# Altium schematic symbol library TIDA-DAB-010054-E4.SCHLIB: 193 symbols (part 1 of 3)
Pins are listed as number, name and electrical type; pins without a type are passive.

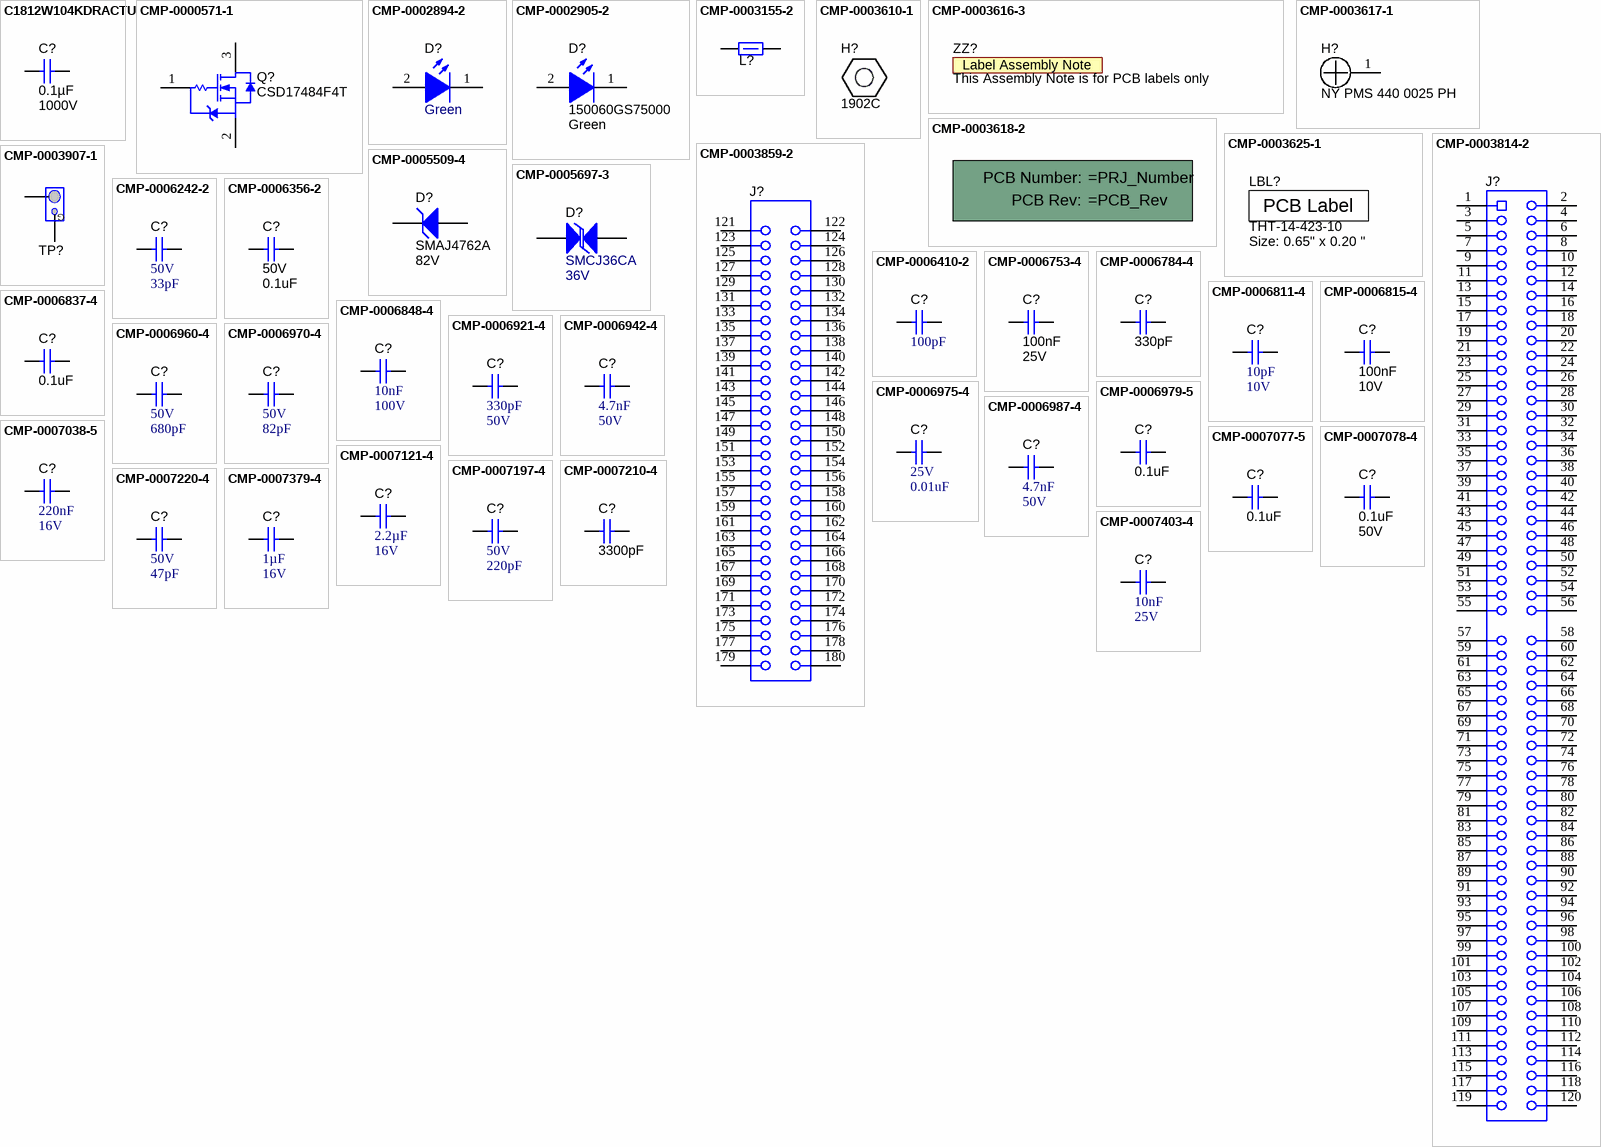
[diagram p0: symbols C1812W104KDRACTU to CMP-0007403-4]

## C1812W104KDRACTU
designator C?, comment ValueDisplayed: 0.1µF  Value2: 1000V  (hidden comment: 1812Y1K00104KXT)
CAP, CERM, 0.1 µF, 1000 V,+/- 10%, X7R, 1812; Manufacturer: Knowles Syfer; Polarized: N; CompType: Capacitor; Value: 0.1uF; U/M: EA; Cap_F: 0.0000001; Tolerance_%: 10; VDC_V: 1000; TaMin_C: -55; TaMax_C: 125; Cap_Case: 1812; SizeArea_mm2: 14.4; SizeAreaWB_mm2: 23.1; SizeX_mm: 4.5; SizeY_mm: 3.2; SizeZ_mm: 2.54; AEC Category: Q200; Green_Lifecycle: Active; Green_REACh: Passed
signal-integrity model Cap
simulation model Cap
footprint 1812_254
pins: 1, 2

## CMP-0000571-1
designator Q?, comment CSD17484F4T
MOSFET, N-CH, 30 V, 3 A, YJJ0003A (PICOSTAR-3); Alternate Manufacturer: None; Manufacturer: Texas Instruments; SizeZ_mm: 0.22; ChType: N; Value2: 0.92 nC; Value1: 0.12; VdsMax_V: 30V; SizeX_mm: 1; SizeY_mm: 0.6; Vgs_V: 12V; Value: 30V; Rdson45_ohm: 0.128; AEC Category: Q101; IdsMax_A: 3A; SizeAreaWB_mm2: 3.2; U/M: EA; QgTyp_nC: 0.92
footprint YJJ0003A (SMD, 3-Leads, Body 1x0.6mm)
pins: 1 G, 2 S, 3 D
1 alternate drawing of the same symbol

## CMP-0002894-2
designator D?, comment value Green  (hidden comment: 150060VS75000)
LED, Green, SMD; Manufacturer: Wurth Elektronik; Manufacturer: Wurth Electronics; Type: AlInGaP; Value2: 2V; Io_A: 20mA; Value1: W
footprint WL-SMCW_GREEN (WURTH)
pins: 1 K, 2 A

## CMP-0002905-2
designator D?, comment 150060GS75000  value Green
LED, Green, SMD; Manufacturer: Wurth Elektronik; Manufacturer: Wurth Electronics; Value1: W; Type: InGaN; Value2: 3.2V; Io_A: 20mA; Angle: 140; Tjmax_C: 85°C
footprint WL-SMCW_GREEN (WURTH)
pins: 1 K, 2 A

## CMP-0003155-2
designator L?, comment 74279228260  (value not drawn)
Ferrite Bead, 26 ohm @ 100 MHz, 6.5 A, 0603; Manufacturer: Wurth Elektronik; Ztyp@1GHz_Ohm: 35.506; ZTyp@100MHz_Ohm: 26; SizeAreaWB_mm2: 4.68; DCR_ohm: 5m; Value1: 0.005 ohm; Value: 26 ohm; Imax_A: 6.5A; SizeZ_mm: 1; SizeX_mm: 1.6; SizeY_mm: 0.8; SizeArea_mm2: 1.28
footprint 0603 (0603 from SM-752 data)
footprint 0603_HV (Ernesto recommended land pattern.  26 mil between pads.)
footprint 0603L (0603 from SM-752 data)
footprint 0603S
footprint 0603M (0603 from SM-752 data)
pins: 1, 2

## CMP-0003610-1
designator H?, comment 1902C
Standoff, Hex, 0.5"L #4-40 Nylon; Manufacturer: Keystone; Manufacturer: Keystone Electronics; CompType: Hardware
footprint Keystone_1902C (Hex Standoff, 4-40 threaded, nylon)

## CMP-0003616-3
designator ZZ?, comment This Assembly Note is for PCB labels only  (no BOM)
Key: AssemblyNoteLabel
footprint AssemblyNoteLabel (Assembly Note for PCB Labels)

## CMP-0003617-1
designator H?, comment NY PMS 440 0025 PH
Machine Screw, Round, #4-40 x 1/4, Nylon, Philips panhead; Manufacturer: B&F Fastener Supply; Manufacturer: B&F Fastener; CompType: Hardware
footprint NY PMS 440 0025 PH (4-40 nylon screw and mounting hole)
footprint NY PMS 440 0025 PH_3Donly (4-40 nylon screw)
pins: 1

## CMP-0003618-2
designator !PCB?, comment Printed Circuit Board  (value not drawn)  (mechanical)
Manufacturer: Any; CompType: PCB
1 alternate drawing of the same symbol

## CMP-0003625-1
designator LBL?, comment THT-14-423-10  Note: Size: 0.65" x 0.20 "
Thermal Transfer Printable Labels, 0.650" W x 0.200" H - 10,000 per roll; Manufacturer: Brady; CompType: Label
footprint Label_650x200 (Thermal Transfer Label)

## CMP-0003814-2
designator J?, comment HSEC8-160-01-L-DV-A-BL  (value not drawn)
C2000 controlCARD-120HSEC connector, SMT; Manufacturer: Samtec; Note: The pin numbering does not match Samtec datasheet
footprint controlCARD-120HSEC (Pads are not numbered according to Samtec datasheet.)
pins: 1, 2, 3, 4, 5, 6, 7, 8, 9, 10, 11, 12, 13, 14, 15, 16, 17, 18, 19, 20, 21, 22, 23, 24, 25, 26, 27, 28, 29, 30, 31, 32, 33, 34, 35, 36, 37, 38, 39, 40, 41, 42, 43, 44, 45, 46, 47, 48, 49, 50, 51, 52, 53, 54, 55, 56, 57, 58, 59, 60, 61, 62, 63, 64, 65, 66, 67, 68, 69, 70, 71, 72, 73, 74, 75, 76, 77, 78, 79, 80, 81, 82, 83, 84, 85, 86, 87, 88, 89, 90, 91, 92, 93, 94, 95, 96, 97, 98, 99, 100, 101, 102, 103, 104, 105, 106, 107, 108, 109, 110, 111, 112, 113, 114, 115, 116, 117, 118, 119, 120

## CMP-0003859-2
designator J?, comment HSEC8-130-01-L-DV-A  (value not drawn)
C2000 controlCARD-180HSEC (60-pin addon) connector, SMT; Manufacturer: Samtec; Note: The pin numbering does not match Samtec datasheet
footprint controlCARD-180HSEC-60pinAddon (Pads are not numbered according to datasheet.)
pins: 121, 122, 123, 124, 125, 126, 127, 128, 129, 130, 131, 132, 133, 134, 135, 136, 137, 138, 139, 140, 141, 142, 143, 144, 145, 146, 147, 148, 149, 150, 151, 152, 153, 154, 155, 156, 157, 158, 159, 160, 161, 162, 163, 164, 165, 166, 167, 168, 169, 170, 171, 172, 173, 174, 175, 176, 177, 178, 179, 180

## CMP-0003907-1
designator TP?, comment GNDP  (value not drawn)  (no BOM)
PIGTAIL; Manufacturer: Texas Instruments; Key: TESTPOINT_PIGTAIL; CompType: Test Point
footprint TESTPOINT_PIGTAIL (Pigtail)
pins: 1, 2

## CMP-0005509-4
designator D?, comment SMAJ4762A  value 82V
Diode, Zener, 82 V, 1 W, SMA; Manufacturer: Micro Commercial Components; Manufacturer: MCC; SizeAreaWB_mm2: 37.3428; SizeZ_mm: 2.87; SizeY_mm: 2.92; SizeArea_mm2: 16.3228; AEC Category: Q101; RJA_CperW: 100; SizeX_mm: 5.59; Power_W: 1W
footprint SMA (Molded Diode, 2-Leads, Body 4.3x2.6mm, IPC Medium Density, based on OnSemi component dimensions and land pattern)
pins: 1 K, 2 A

## CMP-0005697-3
designator D?, comment SMCJ36CA  value 36V
Diode, TVS, Bi, 36 V, 58.1 Vc, SMC; Manufacturer: Littelfuse; Ppk: 1.5kW; Vbr_Min: 40V; SizeX_mm: 8.13; SizeZ_mm: 2.6; SizeAreaWB_mm2: 83.2686; RJA_CperW: 75; AEC Category: Q101; Vbr_Max: 44.2V; SizeArea_mm2: 50.5686; Ipp: 25.9A; Vc: 58.1V; AEC Qualified: N; Value1: 1500W; SizeY_mm: 6.22
footprint SMC_Bi (SMC, no polarity mark)
pins: 1, 2

## CMP-0006242-2
designator C?, comment VDC_V: 50V  ValueDisplayed: 33pF  (hidden comment: C0402C330J5GAC)
CAP, CERM, 33 pF, 50 V, +/- 5%, C0G/NP0, 0402; Manufacturer: Kemet; TaMin_C: -55°C; Polarized: N; SizeAreaWB_mm2: 3; Value1: Unknown; U/M: EA; Value: 33pF; TaMax_C: 125°C; SizeZ_mm: 0.6; SizeX_mm: 1; SizeY_mm: 0.5; Cap_Case: 0402; CompType: Capacitor; AEC Category: Q200
footprint 0402 (0402 from SM-752 data)
footprint 0402S (Based on C0402S footprint from PADS legacy)
footprint 0402L (0402 from SM-752 data)
footprint 0402M (0402 from SM-752 data)
pins: 1, 2

## CMP-0006356-2
designator C?, comment VDC_V: 50V  ValueDisplayed: 0.1uF  (hidden comment: GCM155R71H104KE02D)
CAP, CERM, 0.1 uF, 50 V, +/- 10%, X7R, AEC-Q200 Grade 1, 0402; Manufacturer: MuRata; TaMin_C: -55°C; Polarized: N; SizeAreaWB_mm2: 3; Value1: Unknown; U/M: EA; Value: 0.1uF; TaMax_C: 125°C; SizeZ_mm: 0.6; SizeX_mm: 1; SizeY_mm: 0.5; Cap_Case: 0402; CompType: Capacitor; AEC Qualified: Y; Cap_F: 100nF; AEC Category: Q200
footprint 0402 (0402 from SM-752 data)
footprint 0402S (Based on C0402S footprint from PADS legacy)
footprint 0402L (0402 from SM-752 data)
footprint 0402M (0402 from SM-752 data)
pins: 1, 2

## CMP-0006410-2
designator C?, comment ValueDisplayed: 100pF  (hidden comment: GRM1555C1H101JA01D)
CAP, CERM, 100 pF, 50 V, +/- 5%, C0G/NP0, 0402; Manufacturer: MuRata; TaMin_C: -55°C; Polarized: N; SizeAreaWB_mm2: 3; Value1: Unknown; U/M: EA; Value: 100pF; TaMax_C: 125°C; SizeZ_mm: 0.6; SizeX_mm: 1; SizeY_mm: 0.5; Cap_Case: 0402; Value2: 50V; CompType: Capacitor; AEC Category: Q200
footprint 0402 (0402 from SM-752 data)
footprint 0402S (Based on C0402S footprint from PADS legacy)
footprint 0402L (0402 from SM-752 data)
footprint 0402M (0402 from SM-752 data)
pins: 1, 2

## CMP-0006753-4
designator C?, comment Cap_F: 100nF  VDC_V: 25V  (hidden comment: 06033C104KAT2A)
CAP, CERM, 0.1 uF, 25 V, +/- 10%, X7R, 0603; Manufacturer: AVX; TaMin_C: -55°C; ESR_ohm: 0.05; Polarized: N; SizeAreaWB_mm2: 4.68; Value1: 0.05 ohm; U/M: EA; Value: 0.1uF; TaMax_C: 125°C; SizeZ_mm: 1; SizeX_mm: 1.6; SizeY_mm: 0.8; Cap_Case: 0603; SizeArea_mm2: 1.28; CompType: Capacitor; AEC Category: Q200
footprint 0603 (0603 from SM-752 data)
footprint 0603_HV (Ernesto recommended land pattern.  26 mil between pads.)
footprint 0603L (0603 from SM-752 data)
footprint 0603S
footprint 0603M (0603 from SM-752 data)
pins: 1, 2

## CMP-0006784-4
designator C?, comment ValueDisplayed: 330pF  (hidden comment: 06035A331JAT2A)
CAP, CERM, 330 pF, 50 V, +/- 5%, C0G/NP0, 0603; Manufacturer: AVX; Manufacturer Part Number: 06035A220JAT2A; TaMin_C: -55°C; ESR_ohm: 0.071; Polarized: N; SizeAreaWB_mm2: 4.68; Value1: 0.071 ohm; U/M: EA; Value: 330pF; TaMax_C: 125°C; SizeZ_mm: 1; SizeX_mm: 1.6; SizeY_mm: 0.8; Cap_Case: 0603; Value2: 50V; SizeArea_mm2: 1.28; CompType: Capacitor; AEC Category: Q200
footprint 0603 (0603 from SM-752 data)
footprint 0603_HV (Ernesto recommended land pattern.  26 mil between pads.)
footprint 0603L (0603 from SM-752 data)
footprint 0603S
footprint 0603M (0603 from SM-752 data)
pins: 1, 2

## CMP-0006811-4
designator C?, comment Cap_F: 10pF  VDC_V: 10V  (hidden comment: 0603ZC100KAT2A)
CAP, CERM, 10 pF, 10 V, +/- 10%, X7R, 0603; Manufacturer: AVX; TaMin_C: -55°C; Polarized: N; SizeAreaWB_mm2: 4.68; Value1: Unknown; U/M: EA; Value: 10pF; TaMax_C: 125°C; SizeZ_mm: 1; SizeX_mm: 1.6; SizeY_mm: 0.8; Cap_Case: 0603; SizeArea_mm2: 1.28; CompType: Capacitor; AEC Category: Q200
footprint 0603 (0603 from SM-752 data)
footprint 0603_HV (Ernesto recommended land pattern.  26 mil between pads.)
footprint 0603L (0603 from SM-752 data)
footprint 0603S
footprint 0603M (0603 from SM-752 data)
pins: 1, 2

## CMP-0006815-4
designator C?, comment Cap_F: 100nF  VDC_V: 10V  (hidden comment: 0603ZC104KAT2A)
CAP, CERM, 0.1 uF, 10 V, +/- 10%, X7R, 0603; Manufacturer: AVX; TaMin_C: -55°C; Polarized: N; SizeAreaWB_mm2: 4.68; Value1: Unknown; U/M: EA; Value: 0.1uF; TaMax_C: 125°C; SizeZ_mm: 1; SizeX_mm: 1.6; SizeY_mm: 0.8; Cap_Case: 0603; SizeArea_mm2: 1.28; CompType: Capacitor; AEC Category: Q200
footprint 0603 (0603 from SM-752 data)
footprint 0603_HV (Ernesto recommended land pattern.  26 mil between pads.)
footprint 0603L (0603 from SM-752 data)
footprint 0603S
footprint 0603M (0603 from SM-752 data)
pins: 1, 2

## CMP-0006837-4
designator C?, comment ValueDisplayed: 0.1uF  (hidden comment: 885012206095)
CAP, CERM, 0.1 uF, 50 V, +/- 10%, X7R, 0603; Manufacturer: Wurth Elektronik; TaMin_C: -55°C; Polarized: N; SizeAreaWB_mm2: 4.68; Value1: Unknown; U/M: EA; Value: 0.1uF; TaMax_C: 125°C; SizeZ_mm: 1; SizeX_mm: 1.6; SizeY_mm: 0.8; Cap_Case: 0603; Value2: 50V; SizeArea_mm2: 1.28; CompType: Capacitor; Cap_F: 100nF; AEC Category: Q200
footprint 0603 (0603 from SM-752 data)
footprint 0603_HV (Ernesto recommended land pattern.  26 mil between pads.)
footprint 0603L (0603 from SM-752 data)
footprint 0603S
footprint 0603M (0603 from SM-752 data)
pins: 1, 2

## CMP-0006848-4
designator C?, comment Cap_F: 10nF  VDC_V: 100V  (hidden comment: C0603C103J1RACTU)
CAP, CERM, 0.01 uF, 100 V, +/- 5%, X7R, 0603; Manufacturer: Kemet; TaMin_C: -55°C; Polarized: N; SizeAreaWB_mm2: 4.68; Value1: Unknown; U/M: EA; Value: 0.01uF; TaMax_C: 125°C; SizeZ_mm: 1; SizeX_mm: 1.6; SizeY_mm: 0.8; Cap_Case: 0603; SizeArea_mm2: 1.28; CompType: Capacitor; AEC Category: Q200
footprint 0603 (0603 from SM-752 data)
footprint 0603_HV (Ernesto recommended land pattern.  26 mil between pads.)
footprint 0603L (0603 from SM-752 data)
footprint 0603S
footprint 0603M (0603 from SM-752 data)
pins: 1, 2

## CMP-0006921-4
designator C?, comment Cap_F: 330pF  VDC_V: 50V  (hidden comment: C0603C331K5RACTU)
CAP, CERM, 330 pF, 50 V, +/- 10%, X7R, 0603; Manufacturer: Kemet; TaMin_C: -55°C; Polarized: N; SizeAreaWB_mm2: 4.68; Value1: Unknown; U/M: EA; Value: 330pF; TaMax_C: 125°C; SizeZ_mm: 1; SizeX_mm: 1.6; SizeY_mm: 0.8; Cap_Case: 0603; SizeArea_mm2: 1.28; CompType: Capacitor; AEC Category: Q200
footprint 0603 (0603 from SM-752 data)
footprint 0603_HV (Ernesto recommended land pattern.  26 mil between pads.)
footprint 0603L (0603 from SM-752 data)
footprint 0603S
footprint 0603M (0603 from SM-752 data)
pins: 1, 2

## CMP-0006942-4
designator C?, comment Cap_F: 4.7nF  VDC_V: 50V  (hidden comment: C0603C472J5RACTU)
CAP, CERM, 4700 pF, 50 V, +/- 5%, X7R, 0603; Manufacturer: Kemet; TaMin_C: -55°C; Polarized: N; SizeAreaWB_mm2: 4.68; Value1: Unknown; U/M: EA; Value: 4700pF; TaMax_C: 125°C; SizeZ_mm: 1; SizeX_mm: 1.6; SizeY_mm: 0.8; Cap_Case: 0603; SizeArea_mm2: 1.28; CompType: Capacitor; AEC Category: Q200
footprint 0603 (0603 from SM-752 data)
footprint 0603_HV (Ernesto recommended land pattern.  26 mil between pads.)
footprint 0603L (0603 from SM-752 data)
footprint 0603S
footprint 0603M (0603 from SM-752 data)
pins: 1, 2

## CMP-0006960-4
designator C?, comment VDC_V: 50V  ValueDisplayed: 680pF  (hidden comment: C0603C681K5RACTU)
CAP, CERM, 680 pF, 50 V, +/- 10%, X7R, 0603; Manufacturer: Kemet; TaMin_C: -55°C; Polarized: N; SizeAreaWB_mm2: 4.68; Value1: Unknown; U/M: EA; Value: 680pF; TaMax_C: 125°C; SizeZ_mm: 1; SizeX_mm: 1.6; SizeY_mm: 0.8; Cap_Case: 0603; SizeArea_mm2: 1.28; CompType: Capacitor; AEC Category: Q200
footprint 0603 (0603 from SM-752 data)
footprint 0603_HV (Ernesto recommended land pattern.  26 mil between pads.)
footprint 0603L (0603 from SM-752 data)
footprint 0603S
footprint 0603M (0603 from SM-752 data)
pins: 1, 2

## CMP-0006970-4
designator C?, comment VDC_V: 50V  ValueDisplayed: 82pF  (hidden comment: C0603C820K5GACTU)
CAP, CERM, 82 pF, 50 V, +/- 10%, C0G/NP0, 0603; Manufacturer: Kemet; Manufacturer Part Number: C0603C472J1GAC7867; TaMin_C: -55°C; Polarized: N; SizeAreaWB_mm2: 4.68; Value1: Unknown; U/M: EA; Value: 82pF; TaMax_C: 125°C; SizeZ_mm: 1; SizeX_mm: 1.6; SizeY_mm: 0.8; Cap_Case: 0603; SizeArea_mm2: 1.28; CompType: Capacitor; AEC Category: Q200
footprint 0603 (0603 from SM-752 data)
footprint 0603_HV (Ernesto recommended land pattern.  26 mil between pads.)
footprint 0603L (0603 from SM-752 data)
footprint 0603S
footprint 0603M (0603 from SM-752 data)
pins: 1, 2

## CMP-0006975-4
designator C?, comment VDC_V: 25V  ValueDisplayed: 0.01uF  (hidden comment: C0603H103J3GACTU)
CAP, CERM, 0.01 uF, 25 V, +/- 5%, C0G/NP0, 0603; Manufacturer: Kemet; Manufacturer Part Number: C0603C561J5GACTU; TaMin_C: -55°C; Polarized: N; SizeAreaWB_mm2: 4.68; Value1: Unknown; U/M: EA; Value: 0.01uF; TaMax_C: 200°C; SizeZ_mm: 1; SizeX_mm: 1.6; SizeY_mm: 0.8; Cap_Case: 0603; SizeArea_mm2: 1.28; CompType: Capacitor; Cap_F: 10nF; AEC Category: Q200
footprint 0603 (0603 from SM-752 data)
footprint 0603_HV (Ernesto recommended land pattern.  26 mil between pads.)
footprint 0603L (0603 from SM-752 data)
footprint 0603S
footprint 0603M (0603 from SM-752 data)
pins: 1, 2

## CMP-0006979-5
designator C?, comment ValueDisplayed: 0.1uF  (hidden comment: C0603X104K3RACTU)
CAP, CERM, 0.1 uF, 25 V, +/- 10%, X7R, 0603; Manufacturer: Kemet; Polarized: N; CompType: Capacitor; Value: 0.1uF; U/M: EA; Cap_F: 100nF; Value1: Unknown; VDC_V: 25V; TaMin_C: -55°C; TaMax_C: 125°C; Cap_Case: 0603; SizeArea_mm2: 1.28; SizeAreaWB_mm2: 4.68; SizeX_mm: 1.6; SizeY_mm: 0.8; SizeZ_mm: 1; AEC Category: Q200
footprint 0603 (0603 from SM-752 data)
footprint 0603_HV (Ernesto recommended land pattern.  26 mil between pads.)
footprint 0603L (0603 from SM-752 data)
footprint 0603S
footprint 0603M (0603 from SM-752 data)
pins: 1, 2

## CMP-0006987-4
designator C?, comment Cap_F: 4.7nF  VDC_V: 50V  (hidden comment: C0603X472K5RACTU)
CAP, CERM, 4700 pF, 50 V, +/- 10%, X7R, 0603; Manufacturer: Kemet; TaMin_C: -55°C; Polarized: N; SizeAreaWB_mm2: 4.68; Value1: Unknown; U/M: EA; Value: 4700pF; TaMax_C: 125°C; SizeZ_mm: 1; SizeX_mm: 1.6; SizeY_mm: 0.8; Cap_Case: 0603; SizeArea_mm2: 1.28; CompType: Capacitor; AEC Category: Q200
footprint 0603 (0603 from SM-752 data)
footprint 0603_HV (Ernesto recommended land pattern.  26 mil between pads.)
footprint 0603L (0603 from SM-752 data)
footprint 0603S
footprint 0603M (0603 from SM-752 data)
pins: 1, 2

## CMP-0007038-5
designator C?, comment Cap_F: 220nF  VDC_V: 16V  (hidden comment: C1608X7R1C224K080AC)
CAP, CERM, 0.22 uF, 16 V, +/- 10%, X7R, 0603; Manufacturer: TDK; TaMin_C: -55°C; ESR_ohm: 0.0125; Polarized: N; SizeAreaWB_mm2: 4.68; Value1: 0.0125 ohm; U/M: EA; Value: 0.22uF; TaMax_C: 125°C; SizeZ_mm: 1; SizeX_mm: 1.6; SizeY_mm: 0.8; Cap_Case: 0603; SizeArea_mm2: 1.28; CompType: Capacitor; AEC Category: Q200
footprint 0603 (0603 from SM-752 data)
footprint 0603_HV (Ernesto recommended land pattern.  26 mil between pads.)
footprint 0603L (0603 from SM-752 data)
footprint 0603S
footprint 0603M (0603 from SM-752 data)
pins: 1, 2

## CMP-0007077-5
designator C?, comment ValueDisplayed: 0.1uF  (hidden comment: CGA3E2X7R1E104K080AA)
CAP, CERM, 0.1 uF, 25 V, +/- 10%, X7R, AEC-Q200 Grade 1, 0603; Manufacturer: TDK; TaMin_C: -55°C; Polarized: N; SizeAreaWB_mm2: 4.68; Value1: Unknown; U/M: EA; Value: 0.1uF; TaMax_C: 125°C; SizeZ_mm: 1; SizeX_mm: 1.6; SizeY_mm: 0.8; Cap_Case: 0603; Value2: 25V; SizeArea_mm2: 1.28; CompType: Capacitor; AEC Qualified: Y; Cap_F: 100nF; AEC Category: Q200
footprint 0603 (0603 from SM-752 data)
footprint 0603_HV (Ernesto recommended land pattern.  26 mil between pads.)
footprint 0603L (0603 from SM-752 data)
footprint 0603S
footprint 0603M (0603 from SM-752 data)
pins: 1, 2

## CMP-0007078-4
designator C?, comment value 0.1uF  VDC_V: 50V  (hidden comment: CGA3E2X7R1H104K080AA)
CAP, CERM, 0.1 uF, 50 V, +/- 10%, X7R, AEC-Q200 Grade 1, 0603; Manufacturer: TDK; TaMin_C: -55°C; ESR_ohm: 29.6m; Polarized: N; SizeAreaWB_mm2: 4.68; Value1: 0.0296 ohm; U/M: EA; TaMax_C: 125°C; SizeZ_mm: 1; SizeX_mm: 1.6; SizeY_mm: 0.8; Cap_Case: 0603; SizeArea_mm2: 1.28; CompType: Capacitor; AEC Qualified: Y; Cap_F: 100nF; IRMS_A: 971.99mA; AEC Category: Q200
footprint 0603 (0603 from SM-752 data)
footprint 0603_HV (Ernesto recommended land pattern.  26 mil between pads.)
footprint 0603L (0603 from SM-752 data)
footprint 0603S
footprint 0603M (0603 from SM-752 data)
pins: 1, 2

## CMP-0007121-4
designator C?, comment Cap_F: 2.2µF  VDC_V: 16V  (hidden comment: EMK107BB7225KA-T)
CAP, CERM, 2.2 uF, 16 V, +/- 10%, X7R, 0603; Manufacturer: Taiyo Yuden; TaMin_C: -55°C; Polarized: N; SizeAreaWB_mm2: 4.68; Value1: Unknown; U/M: EA; Value: 2.2uF; TaMax_C: 125°C; SizeZ_mm: 1; SizeX_mm: 1.6; SizeY_mm: 0.8; Cap_Case: 0603; SizeArea_mm2: 1.28; CompType: Capacitor; AEC Category: Q200
footprint 0603 (0603 from SM-752 data)
footprint 0603_HV (Ernesto recommended land pattern.  26 mil between pads.)
footprint 0603L (0603 from SM-752 data)
footprint 0603S
footprint 0603M (0603 from SM-752 data)
pins: 1, 2

## CMP-0007197-4
designator C?, comment VDC_V: 50V  ValueDisplayed: 220pF  (hidden comment: GRM1885C1H221JA01D)
CAP, CERM, 220 pF, 50 V, +/- 5%, C0G/NP0, 0603; Manufacturer: MuRata; TaMin_C: -55°C; Polarized: N; SizeAreaWB_mm2: 4.68; Value1: Unknown; U/M: EA; Value: 220pF; TaMax_C: 125°C; SizeZ_mm: 1; SizeX_mm: 1.6; SizeY_mm: 0.8; Cap_Case: 0603; SizeArea_mm2: 1.28; CompType: Capacitor; AEC Category: Q200
footprint 0603 (0603 from SM-752 data)
footprint 0603_HV (Ernesto recommended land pattern.  26 mil between pads.)
footprint 0603L (0603 from SM-752 data)
footprint 0603S
footprint 0603M (0603 from SM-752 data)
pins: 1, 2

## CMP-0007210-4
designator C?, comment ValueDisplayed: 3300pF  (hidden comment: GRM1885C1H332JA01D)
CAP, CERM, 3300 pF, 50 V, +/- 5%, C0G/NP0, 0603; Manufacturer: MuRata; TaMin_C: -55°C; Polarized: N; SizeAreaWB_mm2: 4.68; Value1: Unknown; U/M: EA; Value: 3300pF; TaMax_C: 125°C; SizeZ_mm: 1; SizeX_mm: 1.6; SizeY_mm: 0.8; Cap_Case: 0603; Value2: 50V; SizeArea_mm2: 1.28; CompType: Capacitor; Cap_F: 3.3nF; AEC Category: Q200
footprint 0603 (0603 from SM-752 data)
footprint 0603_HV (Ernesto recommended land pattern.  26 mil between pads.)
footprint 0603L (0603 from SM-752 data)
footprint 0603S
footprint 0603M (0603 from SM-752 data)
pins: 1, 2

## CMP-0007220-4
designator C?, comment VDC_V: 50V  ValueDisplayed: 47pF  (hidden comment: GRM1885C1H470JA01D)
CAP, CERM, 47 pF, 50 V, +/- 5%, C0G/NP0, 0603; Manufacturer: MuRata; TaMin_C: -55°C; Polarized: N; SizeAreaWB_mm2: 4.68; Value1: Unknown; U/M: EA; Value: 47pF; TaMax_C: 125°C; SizeZ_mm: 1; SizeX_mm: 1.6; SizeY_mm: 0.8; Cap_Case: 0603; SizeArea_mm2: 1.28; CompType: Capacitor; AEC Category: Q200
footprint 0603 (0603 from SM-752 data)
footprint 0603_HV (Ernesto recommended land pattern.  26 mil between pads.)
footprint 0603L (0603 from SM-752 data)
footprint 0603S
footprint 0603M (0603 from SM-752 data)
pins: 1, 2

## CMP-0007379-4
designator C?, comment Cap_F: 1µF  VDC_V: 16V  (hidden comment: GRM188R71C105KA12D)
CAP, CERM, 1 uF, 16 V, +/- 10%, X7R, 0603; Manufacturer: MuRata; TaMin_C: -55°C; ESR_ohm: 0.011; Polarized: N; SizeAreaWB_mm2: 4.68; Value1: 0.011 ohm; U/M: EA; Value: 1uF; TaMax_C: 125°C; SizeZ_mm: 1; SizeX_mm: 1.6; SizeY_mm: 0.8; Cap_Case: 0603; SizeArea_mm2: 1.28; CompType: Capacitor; AEC Category: Q200
footprint 0603 (0603 from SM-752 data)
footprint 0603_HV (Ernesto recommended land pattern.  26 mil between pads.)
footprint 0603L (0603 from SM-752 data)
footprint 0603S
footprint 0603M (0603 from SM-752 data)
pins: 1, 2

## CMP-0007403-4
designator C?, comment Cap_F: 10nF  VDC_V: 25V  (hidden comment: GRM188R71E103KA01D)
CAP, CERM, 0.01 uF, 25 V, +/- 10%, X7R, 0603; Manufacturer: MuRata; TaMin_C: -55°C; Polarized: N; SizeAreaWB_mm2: 4.68; Value1: Unknown; U/M: EA; Value: 0.01uF; TaMax_C: 125°C; SizeZ_mm: 1; SizeX_mm: 1.6; SizeY_mm: 0.8; Cap_Case: 0603; SizeArea_mm2: 1.28; CompType: Capacitor; AEC Category: Q200
footprint 0603 (0603 from SM-752 data)
footprint 0603_HV (Ernesto recommended land pattern.  26 mil between pads.)
footprint 0603L (0603 from SM-752 data)
footprint 0603S
footprint 0603M (0603 from SM-752 data)
pins: 1, 2

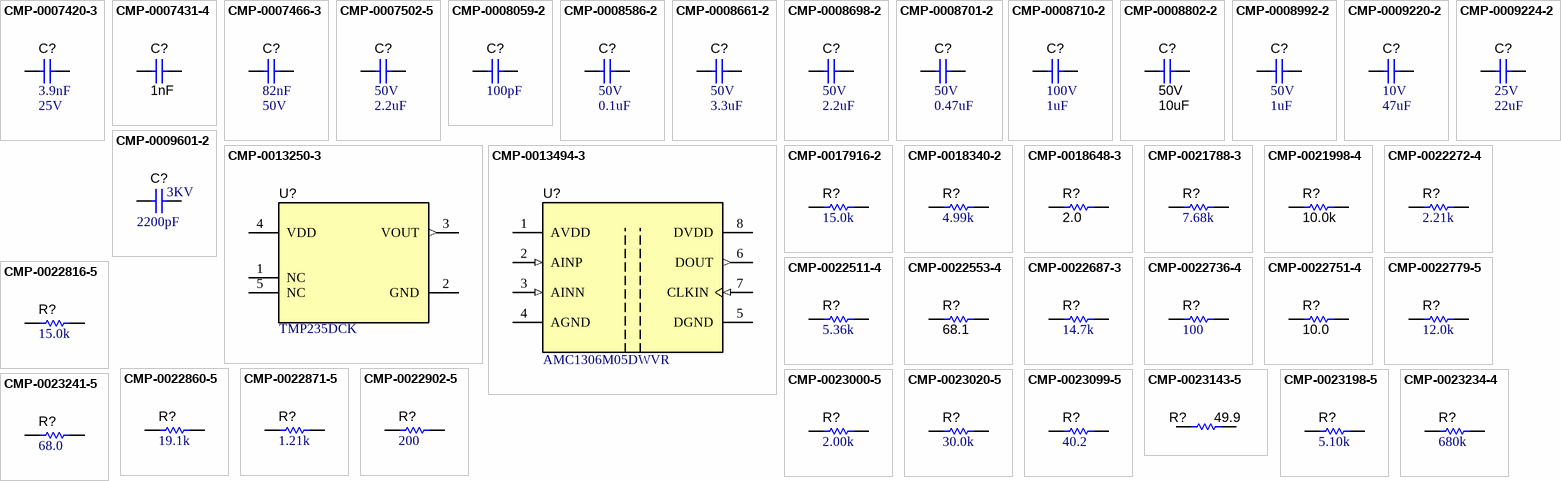
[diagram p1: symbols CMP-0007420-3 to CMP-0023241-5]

## CMP-0007420-3
designator C?, comment Cap_F: 3.9nF  VDC_V: 25V  (hidden comment: 06033C104KAT2A)
CAP, CERM, 3900 pF, 25 V, +/- 10%, X7R, 0603; Manufacturer: MuRata; PartNumber: GRM188R71E392KA01D; TaMin_C: -55°C; Polarized: N; SizeAreaWB_mm2: 4.68; Value1: Unknown; U/M: EA; Value: 3900pF; TaMax_C: 125°C; SizeZ_mm: 1; SizeX_mm: 1.6; SizeY_mm: 0.8; Cap_Case: 0603; SizeArea_mm2: 1.28; CompType: Capacitor; AEC Category: Q200
footprint 0603 (0603 from SM-752 data)
footprint 0603_HV (Ernesto recommended land pattern.  26 mil between pads.)
footprint 0603L (0603 from SM-752 data)
footprint 0603S
footprint 0603M (0603 from SM-752 data)
pins: 1, 2

## CMP-0007431-4
designator C?, comment Cap_F: 1nF  (hidden comment: GRM188R71H102JA01D)
CAP, CERM, 1000 pF, 50 V, +/- 5%, X7R, 0603; Manufacturer: MuRata; TaMin_C: -55°C; Polarized: N; SizeAreaWB_mm2: 4.68; Value1: Unknown; U/M: EA; Value: 1000pF; TaMax_C: 125°C; SizeZ_mm: 1; SizeX_mm: 1.6; SizeY_mm: 0.8; Cap_Case: 0603; Value2: 50V; SizeArea_mm2: 1.28; CompType: Capacitor; AEC Category: Q200
footprint 0603 (0603 from SM-752 data)
footprint 0603_HV (Ernesto recommended land pattern.  26 mil between pads.)
footprint 0603L (0603 from SM-752 data)
footprint 0603S
footprint 0603M (0603 from SM-752 data)
pins: 1, 2

## CMP-0007466-3
designator C?, comment Cap_F: 82nF  VDC_V: 50V  (hidden comment: GRM188R71H823KA93D)
CAP, CERM, 0.082 uF, 50 V, +/- 10%, X7R, 0603; Manufacturer: MuRata; TaMin_C: -55°C; Polarized: N; SizeAreaWB_mm2: 4.68; Value1: Unknown; U/M: EA; TaMax_C: 125°C; SizeZ_mm: 1; SizeX_mm: 1.6; SizeY_mm: 0.8; Cap_Case: 0603; SizeArea_mm2: 1.28; CompType: Capacitor; AEC Category: Q200
footprint 0603 (0603 from SM-752 data)
footprint 0603_HV (Ernesto recommended land pattern.  26 mil between pads.)
footprint 0603L (0603 from SM-752 data)
footprint 0603S
footprint 0603M (0603 from SM-752 data)
pins: 1, 2

## CMP-0007502-5
designator C?, comment VDC_V: 50V  ValueDisplayed: 2.2uF  (hidden comment: GRT188R61H225KE13D)
CAP, CERM, 2.2 uF, 50 V, +/- 10%, X5R, AEC-Q200 Grade 3, 0603; Manufacturer: MuRata; TaMin_C: -55°C; Polarized: N; SizeAreaWB_mm2: 4.68; Value1: Unknown; U/M: EA; Value: 2.2uF; TaMax_C: 85°C; SizeZ_mm: 1; SizeX_mm: 1.6; SizeY_mm: 0.8; Cap_Case: 0603; SizeArea_mm2: 1.28; CompType: Capacitor; AEC Qualified: Y; Cap_F: 2.2µF; AEC Grade: 3; AEC Category: Q200
footprint 0603 (0603 from SM-752 data)
footprint 0603_HV (Ernesto recommended land pattern.  26 mil between pads.)
footprint 0603L (0603 from SM-752 data)
footprint 0603S
footprint 0603M (0603 from SM-752 data)
pins: 1, 2

## CMP-0008059-2
designator C?, comment ValueDisplayed: 100pF  (hidden comment: GRM2165C1H101JA01D)
CAP, CERM, 100 pF, 50 V, +/- 5%, C0G/NP0, 0805; Manufacturer: MuRata; TaMin_C: -55°C; Polarized: N; SizeAreaWB_mm2: 6.75; Value1: Unknown; U/M: EA; Value: 100pF; TaMax_C: 125°C; SizeZ_mm: 1.45; SizeX_mm: 2; SizeY_mm: 1.25; Cap_Case: 0805; Value2: 50V; SizeArea_mm2: 2.5; CompType: Capacitor; AEC Category: Q200
footprint 0805_HV (0805 with 30mil clearance between pads)
footprint 0805M (0805 from SM-752 data)
footprint 0805 (0805 from SM-752 data)
footprint 0805L (0805 from SM-752 data)
footprint 0805_HV1 (Custom footprint based on analyzing multiple manufacturer recommendations)
pins: 1, 2

## CMP-0008586-2
designator C?, comment VDC_V: 50V  ValueDisplayed: 0.1uF  (hidden comment: C1206C104K5RACTU)
CAP, CERM, 0.1 uF, 50 V, +/- 10%, X7R, 1206; Manufacturer: Kemet; Manufacturer Part Number: C1206C104K5RAC-TU; TaMin_C: -55°C; ESR_ohm: 59m; Polarized: N; SizeAreaWB_mm2: 10.92; Value1: 0.059 ohm; U/M: EA; Value: 0.1uF; TaMax_C: 125°C; SizeZ_mm: 1.35; SizeX_mm: 3.2; SizeY_mm: 1.6; Cap_Case: 1206; SizeArea_mm2: 5.12; CompType: Capacitor; Cap_F: 100nF; IRMS_A: 1.2A; AEC Category: Q200
footprint 1206 (1206 from SM-752 data)
footprint 1206L (1206 from SM-752 data)
footprint 1206M (1206 from SM-752 data)
pins: 1, 2

## CMP-0008661-2
designator C?, comment VDC_V: 50V  ValueDisplayed: 3.3uF  (hidden comment: C3216X5R1H335K160AB)
CAP, CERM, 3.3 uF, 50 V, +/- 10%, X5R, 1206; Manufacturer: TDK; TaMin_C: -55°C; ESR_ohm: 4.773m; Polarized: N; SizeAreaWB_mm2: 10.92; Value1: 0.004773 ohm; U/M: EA; Value: 3.3uF; TaMax_C: 85°C; SizeZ_mm: 1.8; SizeX_mm: 3.2; SizeY_mm: 1.6; Cap_Case: 1206_180; SizeArea_mm2: 5.12; CompType: Capacitor; Cap_F: 3.3µF; IRMS_A: 3.3221A; AEC Category: Q200
footprint 1206_180
footprint 1206_180L (1206_180)
footprint 1206_180M (1206_180)
pins: 1, 2

## CMP-0008698-2
designator C?, comment VDC_V: 50V  ValueDisplayed: 2.2uF  (hidden comment: C3216X7R1H225K160AB)
CAP, CERM, 2.2 uF, 50 V, +/- 10%, X7R, 1206; Manufacturer: TDK; TaMin_C: -55°C; ESR_ohm: 5.887m; Polarized: N; SizeAreaWB_mm2: 10.92; Value1: 0.005887 ohm; U/M: EA; Value: 2.2uF; TaMax_C: 125°C; SizeZ_mm: 1.8; SizeX_mm: 3.2; SizeY_mm: 1.6; Cap_Case: 1206_180; SizeArea_mm2: 5.12; CompType: Capacitor; Cap_F: 2.2µF; IRMS_A: 2.9923A; AEC Category: Q200
footprint 1206_180
footprint 1206_180L (1206_180)
footprint 1206_180M (1206_180)
pins: 1, 2

## CMP-0008701-2
designator C?, comment VDC_V: 50V  ValueDisplayed: 0.47uF  (hidden comment: C3216X7R1H474K160AA)
CAP, CERM, 0.47 uF, 50 V, +/- 10%, X7R, 1206; Manufacturer: TDK; TaMin_C: -55°C; ESR_ohm: 9.426m; Polarized: N; SizeAreaWB_mm2: 10.92; Value1: 0.009426 ohm; U/M: EA; Value: 0.47uF; TaMax_C: 125°C; SizeZ_mm: 1.8; SizeX_mm: 3.2; SizeY_mm: 1.6; Cap_Case: 1206_180; SizeArea_mm2: 5.12; CompType: Capacitor; Cap_F: 470nF; IRMS_A: 2.3705A; AEC Category: Q200
footprint 1206_180
footprint 1206_180L (1206_180)
footprint 1206_180M (1206_180)
pins: 1, 2

## CMP-0008710-2
designator C?, comment VDC_V: 100V  ValueDisplayed: 1uF  (hidden comment: C3216X7R2A105K160AA)
CAP, CERM, 1 uF, 100 V, +/- 10%, X7R, 1206; Manufacturer: TDK; TaMin_C: -55°C; ESR_ohm: 4.575m; Polarized: N; SizeAreaWB_mm2: 10.92; Value1: 0.004575 ohm; U/M: EA; Value: 1uF; TaMax_C: 125°C; SizeZ_mm: 1.8; SizeX_mm: 3.2; SizeY_mm: 1.6; Cap_Case: 1206_180; SizeArea_mm2: 5.12; CompType: Capacitor; Cap_F: 1µF; IRMS_A: 3.3964A; AEC Category: Q200
footprint 1206_180
footprint 1206_180L (1206_180)
footprint 1206_180M (1206_180)
pins: 1, 2

## CMP-0008802-2
designator C?, comment VDC_V: 50V  ValueDisplayed: 10uF  (hidden comment: CL31B106KBHNNNE)
CAP, CERM, 10 uF, 50 V, +/- 10%, X7R, 1206; Manufacturer: Samsung; TaMin_C: -55°C; Polarized: N; SizeAreaWB_mm2: 10.92; Value1: Unknown; U/M: EA; Value: 10uF; TaMax_C: 125°C; SizeZ_mm: 1.8; SizeX_mm: 3.2; SizeY_mm: 1.6; Cap_Case: 1206; SizeArea_mm2: 5.12; CompType: Capacitor; Cap_F: 10µF; AEC Category: Q200
footprint 1206_180
footprint 1206_180L (1206_180)
footprint 1206_180M (1206_180)
pins: 1, 2

## CMP-0008992-2
designator C?, comment VDC_V: 50V  ValueDisplayed: 1uF  (hidden comment: GRM31MR71H105KA88L)
CAP, CERM, 1 uF, 50 V, +/- 10%, X7R, 1206; Manufacturer: MuRata; TaMin_C: -55°C; Polarized: N; SizeAreaWB_mm2: 10.92; Value1: Unknown; U/M: EA; Value: 1uF; TaMax_C: 125°C; SizeZ_mm: 1.35; SizeX_mm: 3.2; SizeY_mm: 1.6; Cap_Case: 1206; SizeArea_mm2: 5.12; CompType: Capacitor; Cap_F: 1µF; AEC Category: Q200
footprint 1206 (1206 from SM-752 data)
footprint 1206L (1206 from SM-752 data)
footprint 1206M (1206 from SM-752 data)
pins: 1, 2

## CMP-0009220-2
designator C?, comment VDC_V: 10V  ValueDisplayed: 47uF  (hidden comment: GRM32ER71A476KE15L)
CAP, CERM, 47 uF, 10 V, +/- 10%, X7R, 1210; Manufacturer: MuRata; TaMin_C: -55°C; Polarized: N; SizeAreaWB_mm2: 14.7; Value1: Unknown; U/M: EA; Value: 47uF; TaMax_C: 125°C; SizeZ_mm: 2.7; SizeX_mm: 3.2; SizeY_mm: 2.5; Cap_Case: 1210; SizeArea_mm2: 8; CompType: Capacitor; Cap_F: 47µF; AEC Category: Q200
footprint 1210_270 (1210)
footprint 1210_270L (1210)
footprint 1210_270M (1210)
pins: 1, 2

## CMP-0009224-2
designator C?, comment VDC_V: 25V  ValueDisplayed: 22uF  (hidden comment: GRM32ER71E226KE15L)
CAP, CERM, 22 uF, 25 V, +/- 10%, X7R, 1210; Manufacturer: MuRata; TaMin_C: -55°C; Polarized: N; SizeAreaWB_mm2: 14.7; Value1: Unknown; U/M: EA; Value: 22uF; TaMax_C: 125°C; SizeZ_mm: 2.7; SizeX_mm: 3.2; SizeY_mm: 2.5; Cap_Case: 1210; SizeArea_mm2: 8; CompType: Capacitor; Cap_F: 22µF; AEC Category: Q200
footprint 1210_270 (1210)
footprint 1210_270L (1210)
footprint 1210_270M (1210)
pins: 1, 2

## CMP-0009601-2
designator C?, comment VDC_V: 3KV  ValueDisplayed: 2200pF  (hidden comment: CK45-B3FD222KYVNA)
CAP, CERM, 2200 pF, 3KV, +/- 20%, E, Cap, 7x12x9 mm; Manufacturer: MuRata; Manufacturer Part Number: DE1E3KX222MA4BL01; TaMin_C: -25°C; Polarized: N; SizeAreaWB_mm2: 121.5; Value1: Unknown; U/M: EA; Value: 2200pF; TaMax_C: 85°C; SizeZ_mm: 12.5; SizeX_mm: 11.5; SizeY_mm: 7; Cap_Case: CAPRD1000W60D900H1200; Value2: 250V; SizeArea_mm2: 80.5; CompType: Capacitor; Cap_F: 2.2nF; AEC Category: Q200
footprint CAPRD1000W60D900H1200 (Disk, Radial Capacitor)
pins: 1, 2

## CMP-0013250-3
designator U?, comment TMP235DCK
TMP235DCK, DCK0005A (SOT-5); Manufacturer: Texas Instruments; SizeX_mm: 2.1; SizeY_mm: 2.0; CompType: IC; SizeZ_mm: 1.1; SizeArea_mm2: 4.2; SizeAreaWB_mm2: 9.3; AEC Category: Q200; AEC Qualified: N
footprint DCK0005A_N (SOT353, 5-Leads, Body 2x1.3mm, Pitch 0.65mm, Lead Span 2.1mm, IPC Medium Density)
footprint DCK0005A_M (SOT353, 5-Leads, Body 2x1.3mm, Pitch 0.65mm, Lead Span 2.1mm, IPC Low Density)
footprint DCK0005A_L (SOT353, 5-Leads, Body 2x1.3mm, Pitch 0.65mm, Lead Span 2.1mm, IPC High Density)
pins: 1 NC, 2 GND (power), 3 VOUT (out), 4 VDD (power), 5 NC

## CMP-0013494-3
designator U?, comment AMC1306M05DWVR
Small Reinforced Isolated Modulator With +/-50mV Input and CMOS Interface, DWV0008A (SOIC-8); Manufacturer: Texas Instruments; SizeArea_mm2: 67.275; CompType: IC; AEC Qualified: N; SizeX_mm: 11.5; SizeZ_mm: 2.8; SizeAreaWB_mm2: 105.975; AEC Category: Q200; Rating: Catalog; SizeY_mm: 5.85
footprint DWV0008A (SOIC, 8-Leads, Body 5.95x7.6mm (max), Pitch 1.27mm)
pins: 1 AVDD (power), 2 AINP (in), 3 AINN (in), 4 AGND (power), 5 DGND (power), 6 DOUT (out), 7 CLKIN (in), 8 DVDD (power)
1 alternate drawing of the same symbol

## CMP-0017916-2
designator R?, comment ValueDisplayed: 15.0k  (hidden comment: RC1206FR-0715KL)
RES, 15.0 k, 1%, 0.25 W, 1206; Manufacturer: Yageo America; Power_W: 250mW; TempCo: 100 ppm/C; Value_Code: 15k0; U/M: EA; Value: 15.0k; EIA_Code: E96; Res_ohm: 15k; SizeX_mm: 3.2; SizeY_mm: 1.6; SizeZ_mm: 1.35; Value2: 0.25W; SizeArea_mm2: 5.12; CompType: Resistor; VDC_V: 200V; AEC Category: Q200
footprint 1206 (1206 from SM-752 data)
footprint 1206L (1206 from SM-752 data)
footprint 1206M (1206 from SM-752 data)
pins: 1, 2

## CMP-0018340-2
designator R?, comment ValueDisplayed: 4.99k  (hidden comment: RC1206FR-074K99L)
RES, 4.99 k, 1%, 0.25 W, 1206; Manufacturer: Yageo America; Power_W: 250mW; TempCo: 100 ppm/C; Value_Code: 4k99; U/M: EA; Value: 4.99k; EIA_Code: E96; SizeX_mm: 3.2; SizeY_mm: 1.6; SizeZ_mm: 1.35; Value2: 0.25W; SizeArea_mm2: 5.12; CompType: Resistor; VDC_V: 200V; AEC Category: Q200
footprint 1206 (1206 from SM-752 data)
footprint 1206L (1206 from SM-752 data)
footprint 1206M (1206 from SM-752 data)
pins: 1, 2

## CMP-0018648-3
designator R?, comment ValueDisplayed: 2.0  (hidden comment: CRCW12062R00JNEA)
RES, 2.0, 5%, 0.25 W, AEC-Q200 Grade 0, 1206; Manufacturer: Vishay-Dale; Manufacturer: Vishay/Dale; Power_W: 250mW; TempCo: 200 ppm/C; Value_Code: 2R00; Value: 2.0; EIA_Code: E24; Res_ohm: 2; SizeX_mm: 3.2; SizeY_mm: 1.6; SizeZ_mm: 1.35; Value2: 0.25W; SizeArea_mm2: 5.12; CompType: Resistor; AEC Qualified: Y; VDC_V: 200V; AEC Category: Q200; AEC Grade: 0
footprint 1206 (1206 from SM-752 data)
footprint 1206L (1206 from SM-752 data)
footprint 1206M (1206 from SM-752 data)
pins: 1, 2

## CMP-0021788-3
designator R?, comment ValueDisplayed: 7.68k  (hidden comment: ERJ-6ENF7681V)
RES, 7.68 k, 1%, 0.125 W, AEC-Q200 Grade 0, 0805; Manufacturer: Panasonic; Power_W: 125mW; TempCo: 100 ppm/C; Value_Code: 7k68; Value: 7.68k; EIA_Code: E96; SizeX_mm: 2; SizeY_mm: 1.25; SizeZ_mm: 1.45; Value2: 0.125W; SizeArea_mm2: 2.5; CompType: Resistor; AEC Qualified: Y; AEC Category: Q200; AEC Grade: 0; SizeAreaWB_mm2: 6.75
footprint 0805_HV (0805 with 30mil clearance between pads)
footprint 0805_HV1 (Custom footprint based on analyzing multiple manufacturer recommendations)
footprint 0805 (0805 from SM-752 data)
footprint 0805M (0805 from SM-752 data)
footprint 0805L (0805 from SM-752 data)
pins: 1, 2

## CMP-0021998-4
designator R?, comment ValueDisplayed: 10.0k  (hidden comment: CRCW060310K0FKEA)
RES, 10.0 k, 1%, 0.1 W, AEC-Q200 Grade 0, 0603; Manufacturer: Vishay-Dale; Manufacturer: Vishay / Dale; CompType: Resistor; Value: 10.0k; Res_ohm: 10k; Value_Code: 10k0; Power_W: 100mW; Value2: 0.1W; VDC_V: 75V; TempCo: 100 ppm/C; SizeArea_mm2: 1.28; SizeX_mm: 1.6; SizeY_mm: 0.8; SizeZ_mm: 1; EIA_Code: E96; AEC Category: Q200; AEC Qualified: Y; AEC Grade: 0
footprint 0603 (0603 from SM-752 data)
footprint 0603_HV (Ernesto recommended land pattern.  26 mil between pads.)
footprint 0603L (0603 from SM-752 data)
footprint 0603S
footprint 0603M (0603 from SM-752 data)
pins: 1, 2

## CMP-0022272-4
designator R?, comment ValueDisplayed: 2.21k  (hidden comment: CRCW06032K21FKEA)
RES, 2.21 k, 1%, 0.1 W, AEC-Q200 Grade 0, 0603; Manufacturer: Vishay-Dale; Manufacturer: Vishay / Dale; Power_W: 100mW; TempCo: 100 ppm/C; Value_Code: 2k21; Value: 2.21k; EIA_Code: E96; SizeX_mm: 1.6; SizeY_mm: 0.8; SizeZ_mm: 1; Value2: 0.1W; SizeArea_mm2: 1.28; CompType: Resistor; AEC Qualified: Y; VDC_V: 75V; AEC Category: Q200; AEC Grade: 0
footprint 0603 (0603 from SM-752 data)
footprint 0603_HV (Ernesto recommended land pattern.  26 mil between pads.)
footprint 0603L (0603 from SM-752 data)
footprint 0603S
footprint 0603M (0603 from SM-752 data)
pins: 1, 2

## CMP-0022511-4
designator R?, comment ValueDisplayed: 5.36k  (hidden comment: CRCW06035K36FKEA)
RES, 5.36 k, 1%, 0.1 W, AEC-Q200 Grade 0, 0603; Manufacturer: Vishay-Dale; Manufacturer: Vishay / Dale; Power_W: 100mW; TempCo: 100 ppm/C; Value_Code: 5k36; Value: 5.36k; EIA_Code: E96; SizeX_mm: 1.6; SizeY_mm: 0.8; SizeZ_mm: 1; Value2: 0.1W; SizeArea_mm2: 1.28; CompType: Resistor; AEC Qualified: Y; VDC_V: 75V; AEC Category: Q200; AEC Grade: 0
footprint 0603 (0603 from SM-752 data)
footprint 0603_HV (Ernesto recommended land pattern.  26 mil between pads.)
footprint 0603L (0603 from SM-752 data)
footprint 0603S
footprint 0603M (0603 from SM-752 data)
pins: 1, 2

## CMP-0022553-4
designator R?, comment ValueDisplayed: 68.1  (hidden comment: CRCW060368R1FKEA)
RES, 68.1, 1%, 0.1 W, AEC-Q200 Grade 0, 0603; Manufacturer: Vishay-Dale; Manufacturer: Vishay / Dale; CompType: Resistor; Value: 68.1; Value_Code: 68R1; Power_W: 100mW; Value2: 0.1W; VDC_V: 75V; TempCo: 100 ppm/C; SizeArea_mm2: 1.28; SizeX_mm: 1.6; SizeY_mm: 0.8; SizeZ_mm: 1; EIA_Code: E96; AEC Category: Q200; AEC Qualified: Y; AEC Grade: 0
footprint 0603 (0603 from SM-752 data)
footprint 0603_HV (Ernesto recommended land pattern.  26 mil between pads.)
footprint 0603L (0603 from SM-752 data)
footprint 0603S
footprint 0603M (0603 from SM-752 data)
pins: 1, 2

## CMP-0022687-3
designator R?, comment ValueDisplayed: 14.7k  (hidden comment: ERJ-3EKF1472V)
RES, 14.7 k, 1%, 0.1 W, AEC-Q200 Grade 0, 0603; Manufacturer: Panasonic; Power_W: 100mW; TempCo: 100 ppm/C; Value_Code: 14k7; U/M: EA; Value: 14.7k; EIA_Code: E96; SizeX_mm: 1.6; SizeY_mm: 0.8; SizeZ_mm: 1; Value2: 0.1W; SizeArea_mm2: 1.28; CompType: Resistor; AEC Qualified: Y; VDC_V: 50V; AEC Grade: 0; AEC Category: Q200
footprint 0603 (0603 from SM-752 data)
footprint 0603_HV (Ernesto recommended land pattern.  26 mil between pads.)
footprint 0603L (0603 from SM-752 data)
footprint 0603S
footprint 0603M (0603 from SM-752 data)
pins: 1, 2

## CMP-0022736-4
designator R?, comment ValueDisplayed: 100  (hidden comment: RC0603FR-07100RL)
RES, 100, 1%, 0.1 W, 0603; Manufacturer: Yageo; Power_W: 100mW; TempCo: 100 ppm/C; Value_Code: 100R; Value: 100; EIA_Code: E96; SizeX_mm: 1.6; SizeY_mm: 0.8; SizeZ_mm: 1; Value2: 0.1W; SizeArea_mm2: 1.28; CompType: Resistor; AEC Qualified: N; VDC_V: 75V; AEC Category: Q200; SizeAreaWB_mm2: 4.68
footprint 0603 (0603 from SM-752 data)
footprint 0603_HV (Ernesto recommended land pattern.  26 mil between pads.)
footprint 0603L (0603 from SM-752 data)
footprint 0603S
footprint 0603M (0603 from SM-752 data)
pins: 1, 2

## CMP-0022751-4
designator R?, comment ValueDisplayed: 10.0  (hidden comment: RC0603FR-0710RL)
RES, 10.0, 1%, 0.1 W, 0603; Manufacturer: Yageo; CompType: Resistor; Value: 10.0; Res_ohm: 10; Value_Code: 10R0; Power_W: 100mW; Value2: 0.1W; VDC_V: 75V; TempCo: 100 ppm/C; SizeArea_mm2: 1.28; SizeX_mm: 1.6; SizeY_mm: 0.8; SizeZ_mm: 1; EIA_Code: E96; AEC Category: Q200; AEC Qualified: N; SizeAreaWB_mm2: 4.68
footprint 0603 (0603 from SM-752 data)
footprint 0603_HV (Ernesto recommended land pattern.  26 mil between pads.)
footprint 0603L (0603 from SM-752 data)
footprint 0603S
footprint 0603M (0603 from SM-752 data)
pins: 1, 2

## CMP-0022779-5
designator R?, comment ValueDisplayed: 12.0k  (hidden comment: RC0603FR-0712KL)
RES, 12.0 k, 1%, 0.1 W, 0603; Manufacturer: Yageo; Power_W: 100mW; TempCo: 100 ppm/C; Value_Code: 12k0; Value: 12.0k; Res_ohm: 12k; SizeX_mm: 1.6; SizeY_mm: 0.8; SizeZ_mm: 1; Value2: 0.1W; SizeArea_mm2: 1.28; CompType: Resistor; AEC Qualified: N; VDC_V: 75V; AEC Category: Q200; SizeAreaWB_mm2: 4.68
footprint 0603 (0603 from SM-752 data)
footprint 0603_HV (Ernesto recommended land pattern.  26 mil between pads.)
footprint 0603L (0603 from SM-752 data)
footprint 0603S
footprint 0603M (0603 from SM-752 data)
pins: 1, 2

## CMP-0022816-5
designator R?, comment ValueDisplayed: 15.0k  (hidden comment: RC0603FR-0715KL)
RES, 15.0 k, 1%, 0.1 W, 0603; Manufacturer: Yageo; Power_W: 100mW; TempCo: 100 ppm/C; Value_Code: 15k0; Value: 15.0k; EIA_Code: E96; Res_ohm: 15k; SizeX_mm: 1.6; SizeY_mm: 0.8; SizeZ_mm: 1; Value2: 0.1W; SizeArea_mm2: 1.28; CompType: Resistor; AEC Qualified: N; VDC_V: 75V; AEC Category: Q200; SizeAreaWB_mm2: 4.68
footprint 0603 (0603 from SM-752 data)
footprint 0603_HV (Ernesto recommended land pattern.  26 mil between pads.)
footprint 0603L (0603 from SM-752 data)
footprint 0603S
footprint 0603M (0603 from SM-752 data)
pins: 1, 2

## CMP-0022860-5
designator R?, comment ValueDisplayed: 19.1k  (hidden comment: RC0603FR-0719K1L)
RES, 19.1 k, 1%, 0.1 W, 0603; Manufacturer: Yageo; Power_W: 100mW; TempCo: 100 ppm/C; Value_Code: 19k1; Value: 19.1k; EIA_Code: E96; SizeX_mm: 1.6; SizeY_mm: 0.8; SizeZ_mm: 1; Value2: 0.1W; SizeArea_mm2: 1.28; CompType: Resistor; AEC Qualified: N; VDC_V: 75V; AEC Category: Q200; SizeAreaWB_mm2: 4.68
footprint 0603 (0603 from SM-752 data)
footprint 0603_HV (Ernesto recommended land pattern.  26 mil between pads.)
footprint 0603L (0603 from SM-752 data)
footprint 0603S
footprint 0603M (0603 from SM-752 data)
pins: 1, 2

## CMP-0022871-5
designator R?, comment ValueDisplayed: 1.21k  (hidden comment: RC0603FR-071K21L)
RES, 1.21 k, 1%, 0.1 W, 0603; Manufacturer: Yageo; Power_W: 100mW; TempCo: 100 ppm/C; Value_Code: 1k21; Value: 1.21k; EIA_Code: E96; SizeX_mm: 1.6; SizeY_mm: 0.8; SizeZ_mm: 1; Value2: 0.1W; SizeArea_mm2: 1.28; CompType: Resistor; AEC Qualified: N; VDC_V: 75V; AEC Category: Q200; SizeAreaWB_mm2: 4.68
footprint 0603 (0603 from SM-752 data)
footprint 0603_HV (Ernesto recommended land pattern.  26 mil between pads.)
footprint 0603L (0603 from SM-752 data)
footprint 0603S
footprint 0603M (0603 from SM-752 data)
pins: 1, 2

## CMP-0022902-5
designator R?, comment ValueDisplayed: 200  (hidden comment: RC0603FR-07200RL)
RES, 200, 1%, 0.1 W, 0603; Manufacturer: Yageo; Power_W: 100mW; TempCo: 100 ppm/C; Value_Code: 200R; Value: 200; EIA_Code: E96; SizeX_mm: 1.6; SizeY_mm: 0.8; SizeZ_mm: 1; Value2: 0.1W; SizeArea_mm2: 1.28; CompType: Resistor; AEC Qualified: N; VDC_V: 75V; AEC Category: Q200; SizeAreaWB_mm2: 4.68
footprint 0603 (0603 from SM-752 data)
footprint 0603_HV (Ernesto recommended land pattern.  26 mil between pads.)
footprint 0603L (0603 from SM-752 data)
footprint 0603S
footprint 0603M (0603 from SM-752 data)
pins: 1, 2

## CMP-0023000-5
designator R?, comment ValueDisplayed: 2.00k  (hidden comment: RC0603FR-072KL)
RES, 2.00 k, 1%, 0.1 W, 0603; Manufacturer: Yageo; Power_W: 100mW; TempCo: 100 ppm/C; Value_Code: 2k00; Value: 2.00k; EIA_Code: E96; Res_ohm: 2k; SizeX_mm: 1.6; SizeY_mm: 0.8; SizeZ_mm: 1; Value2: 0.1W; SizeArea_mm2: 1.28; CompType: Resistor; AEC Qualified: N; VDC_V: 75V; AEC Category: Q200; SizeAreaWB_mm2: 4.68
footprint 0603 (0603 from SM-752 data)
footprint 0603_HV (Ernesto recommended land pattern.  26 mil between pads.)
footprint 0603L (0603 from SM-752 data)
footprint 0603S
footprint 0603M (0603 from SM-752 data)
pins: 1, 2

## CMP-0023020-5
designator R?, comment ValueDisplayed: 30.0k  (hidden comment: RC0603FR-0730KL)
RES, 30.0 k, 1%, 0.1 W, 0603; Manufacturer: Yageo; Power_W: 100mW; TempCo: 100 ppm/C; Value_Code: 30k0; Value: 30.0k; Res_ohm: 30k; SizeX_mm: 1.6; SizeY_mm: 0.8; SizeZ_mm: 1; Value2: 0.1W; SizeArea_mm2: 1.28; CompType: Resistor; AEC Qualified: N; VDC_V: 75V; AEC Category: Q200; SizeAreaWB_mm2: 4.68
footprint 0603 (0603 from SM-752 data)
footprint 0603_HV (Ernesto recommended land pattern.  26 mil between pads.)
footprint 0603L (0603 from SM-752 data)
footprint 0603S
footprint 0603M (0603 from SM-752 data)
pins: 1, 2

## CMP-0023099-5
designator R?, comment ValueDisplayed: 40.2  (hidden comment: RC0603FR-0740R2L)
RES, 40.2, 1%, 0.1 W, 0603; Manufacturer: Yageo; Power_W: 100mW; TempCo: 100 ppm/C; Value_Code: 40R2; Value: 40.2; EIA_Code: E96; SizeX_mm: 1.6; SizeY_mm: 0.8; SizeZ_mm: 1; Value2: 0.1W; SizeArea_mm2: 1.28; CompType: Resistor; AEC Qualified: N; VDC_V: 75V; AEC Category: Q200; SizeAreaWB_mm2: 4.68
footprint 0603 (0603 from SM-752 data)
footprint 0603_HV (Ernesto recommended land pattern.  26 mil between pads.)
footprint 0603L (0603 from SM-752 data)
footprint 0603S
footprint 0603M (0603 from SM-752 data)
pins: 1, 2

## CMP-0023143-5
designator R?, comment ValueDisplayed: 49.9  (hidden comment: RC0603FR-0749R9L)
RES, 49.9, 1%, 0.1 W, 0603; Manufacturer: Yageo; Power_W: 100mW; TempCo: 100 ppm/C; Value_Code: 49R9; Value: 49.9; EIA_Code: E96; SizeX_mm: 1.6; SizeY_mm: 0.8; SizeZ_mm: 1; Value2: 0.1W; SizeArea_mm2: 1.28; CompType: Resistor; AEC Qualified: N; VDC_V: 75V; AEC Category: Q200; SizeAreaWB_mm2: 4.68
footprint 0603 (0603 from SM-752 data)
footprint 0603_HV (Ernesto recommended land pattern.  26 mil between pads.)
footprint 0603L (0603 from SM-752 data)
footprint 0603S
footprint 0603M (0603 from SM-752 data)
pins: 1, 2

## CMP-0023198-5
designator R?, comment ValueDisplayed: 5.10k  (hidden comment: RC0603FR-075K1L)
RES, 5.10 k, 1%, 0.1 W, 0603; Manufacturer: Yageo; Power_W: 100mW; TempCo: 100 ppm/C; Value_Code: 5k10; Value: 5.10k; Res_ohm: 5.1k; SizeX_mm: 1.6; SizeY_mm: 0.8; SizeZ_mm: 1; Value2: 0.1W; SizeArea_mm2: 1.28; CompType: Resistor; AEC Qualified: N; VDC_V: 75V; AEC Category: Q200; SizeAreaWB_mm2: 4.68
footprint 0603 (0603 from SM-752 data)
footprint 0603_HV (Ernesto recommended land pattern.  26 mil between pads.)
footprint 0603L (0603 from SM-752 data)
footprint 0603S
footprint 0603M (0603 from SM-752 data)
pins: 1, 2

## CMP-0023234-4
designator R?, comment ValueDisplayed: 680k  (hidden comment: RC0603FR-07680KL)
RES, 680 k, 1%, 0.1 W, 0603; Manufacturer: Yageo; Power_W: 100mW; TempCo: 100 ppm/C; Value: 680k; SizeX_mm: 1.6; SizeY_mm: 0.8; SizeZ_mm: 1; Value2: 0.1W; SizeArea_mm2: 1.28; CompType: Resistor; AEC Qualified: N; VDC_V: 75V; AEC Category: Q200; SizeAreaWB_mm2: 4.68
footprint 0603 (0603 from SM-752 data)
footprint 0603_HV (Ernesto recommended land pattern.  26 mil between pads.)
footprint 0603L (0603 from SM-752 data)
footprint 0603S
footprint 0603M (0603 from SM-752 data)
pins: 1, 2

## CMP-0023241-5
designator R?, comment ValueDisplayed: 68.0  (hidden comment: RC0603FR-0768RL)
RES, 68.0, 1%, 0.1 W, 0603; Manufacturer: Yageo; Power_W: 100mW; TempCo: 100 ppm/C; Value_Code: 68R0; Value: 68.0; Res_ohm: 68; SizeX_mm: 1.6; SizeY_mm: 0.8; SizeZ_mm: 1; Value2: 0.1W; SizeArea_mm2: 1.28; CompType: Resistor; AEC Qualified: N; VDC_V: 75V; AEC Category: Q200; SizeAreaWB_mm2: 4.68
footprint 0603 (0603 from SM-752 data)
footprint 0603_HV (Ernesto recommended land pattern.  26 mil between pads.)
footprint 0603L (0603 from SM-752 data)
footprint 0603S
footprint 0603M (0603 from SM-752 data)
pins: 1, 2

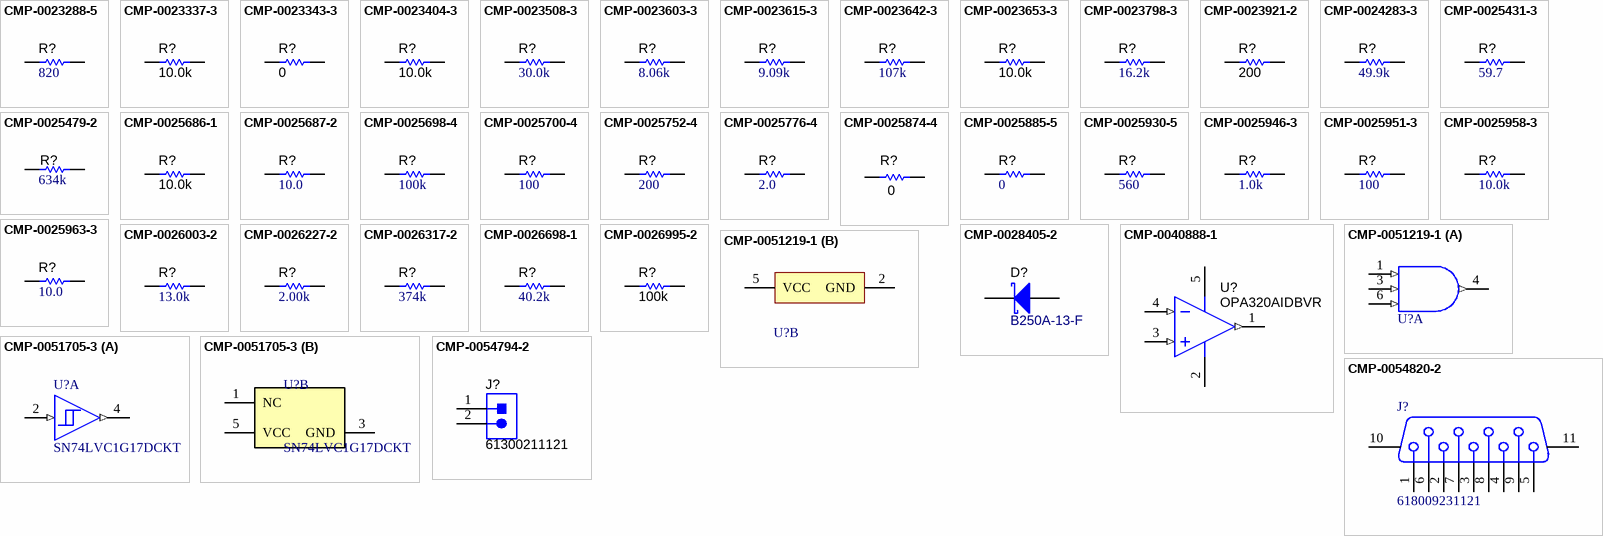
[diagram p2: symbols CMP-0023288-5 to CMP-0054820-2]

## CMP-0023288-5
designator R?, comment ValueDisplayed: 820  (hidden comment: RC0603FR-07820RL)
RES, 820, 1%, 0.1 W, 0603; Manufacturer: Yageo; Power_W: 100mW; TempCo: 100 ppm/C; Value_Code: 820R; Value: 820; SizeX_mm: 1.6; SizeY_mm: 0.8; SizeZ_mm: 1; Value2: 0.1W; SizeArea_mm2: 1.28; CompType: Resistor; AEC Qualified: N; VDC_V: 75V; AEC Category: Q200; SizeAreaWB_mm2: 4.68
footprint 0603 (0603 from SM-752 data)
footprint 0603_HV (Ernesto recommended land pattern.  26 mil between pads.)
footprint 0603L (0603 from SM-752 data)
footprint 0603S
footprint 0603M (0603 from SM-752 data)
pins: 1, 2

## CMP-0023337-3
designator R?, comment ValueDisplayed: 10.0k  (hidden comment: CRCW06030000Z0EA)
RES, 10.0 k, 1%, 0.1 W, 0603; Manufacturer: Vishay Draloric; PartNumber: RCG060310K0FKEA; Power_W: 100mW; TempCo: 100 ppm/C; Value_Code: 10k0; U/M: EA; Value: 10.0k; EIA_Code: E96; Res_ohm: 10k; SizeX_mm: 1.6; SizeY_mm: 0.8; SizeZ_mm: 1; Value2: 0.1W; SizeArea_mm2: 1.28; CompType: Resistor; AEC Qualified: N; VDC_V: 75V; AEC Category: Q200
footprint 0603 (0603 from SM-752 data)
footprint 0603_HV (Ernesto recommended land pattern.  26 mil between pads.)
footprint 0603L (0603 from SM-752 data)
footprint 0603S
footprint 0603M (0603 from SM-752 data)
pins: 1, 2

## CMP-0023343-3
designator R?, comment ValueDisplayed: 0  (hidden comment: RMCF0603ZT0R00)
RES, 0, 1%, 0.1 W, AEC-Q200 Grade 0, 0603; Manufacturer: Stackpole Electronics Inc; Power_W: 100mW; TempCo: ppm/C; U/M: EA; Value: 0; SizeX_mm: 1.6; SizeY_mm: 0.8; SizeZ_mm: 1; Value2: 0.1W; SizeArea_mm2: 1.28; CompType: Resistor; AEC Qualified: Y; AEC Category: Q200
footprint 0603 (0603 from SM-752 data)
footprint 0603_HV (Ernesto recommended land pattern.  26 mil between pads.)
footprint 0603L (0603 from SM-752 data)
footprint 0603S
footprint 0603M (0603 from SM-752 data)
pins: 1, 2

## CMP-0023404-3
designator R?, comment ValueDisplayed: 10.0k  (hidden comment: RG1608P-103-B-T5)
RES, 10.0 k, 0.1%, 0.1 W, 0603; Manufacturer: Susumu Co Ltd; CompType: Resistor; Value: 10.0k; Res_ohm: 10k; Value_Code: 10k0; Power_W: 100mW; Value2: 0.1W; VDC_V: 75V; TempCo: 25 ppm/C; SizeArea_mm2: 1.28; SizeX_mm: 1.6; SizeY_mm: 0.8; SizeZ_mm: 1; EIA_Code: E192; U/M: EA; AEC Category: Q200
footprint 0603 (0603 from SM-752 data)
footprint 0603_HV (Ernesto recommended land pattern.  26 mil between pads.)
footprint 0603L (0603 from SM-752 data)
footprint 0603S
footprint 0603M (0603 from SM-752 data)
pins: 1, 2

## CMP-0023508-3
designator R?, comment ValueDisplayed: 30.0k  (hidden comment: RG1608P-303-B-T5)
RES, 30.0 k, 0.1%, 0.1 W, 0603; Manufacturer: Susumu Co Ltd; Power_W: 100mW; TempCo: 25 ppm/C; Value_Code: 30k0; U/M: EA; Value: 30.0k; Res_ohm: 30k; SizeX_mm: 1.6; SizeY_mm: 0.8; SizeZ_mm: 1; Value2: 0.1W; SizeArea_mm2: 1.28; CompType: Resistor; VDC_V: 75V; AEC Category: Q200
footprint 0603 (0603 from SM-752 data)
footprint 0603_HV (Ernesto recommended land pattern.  26 mil between pads.)
footprint 0603L (0603 from SM-752 data)
footprint 0603S
footprint 0603M (0603 from SM-752 data)
pins: 1, 2

## CMP-0023603-3
designator R?, comment ValueDisplayed: 8.06k  (hidden comment: RT0603DRE079K2L)
RES, 8.06 k, 0.1%, 0.1 W, 0603; Manufacturer: Susumu Co Ltd; PartNumber: RG1608P-8061-B-T5; Power_W: 100mW; TempCo: 25 ppm/C; Value_Code: 8k06; U/M: EA; Value: 8.06k; EIA_Code: E192; SizeX_mm: 1.6; SizeY_mm: 0.8; SizeZ_mm: 1; Value2: 0.1W; SizeArea_mm2: 1.28; CompType: Resistor; VDC_V: 75V; AEC Category: Q200
footprint 0603 (0603 from SM-752 data)
footprint 0603_HV (Ernesto recommended land pattern.  26 mil between pads.)
footprint 0603L (0603 from SM-752 data)
footprint 0603S
footprint 0603M (0603 from SM-752 data)
pins: 1, 2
